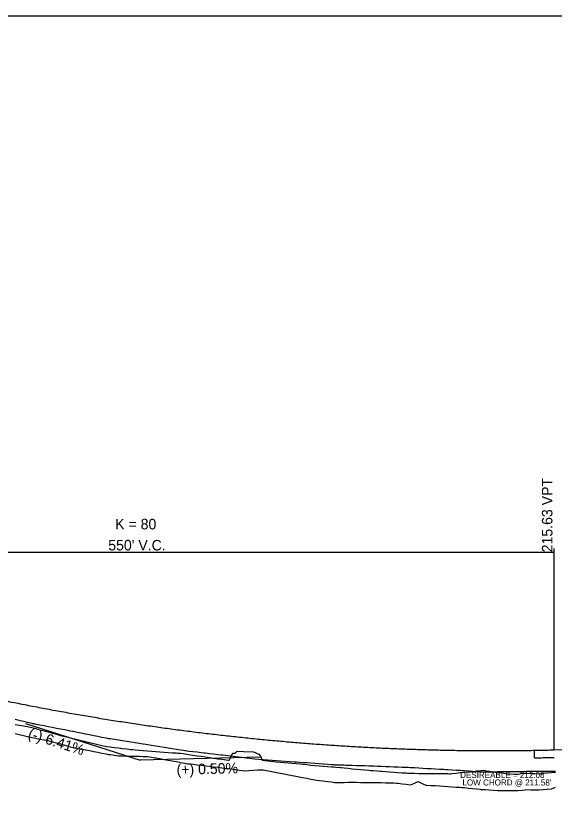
# Model space of a CAD drawing. Extents: x 2224795 to 2228395, y 930927 to 933127.
# Drawn here: x 2226072 to 2226430, y 932027 to 932554 of the extents above; entities that cross this region are included whole.
import ezdxf

# ---------------------------------------------------------------- set-up
doc = ezdxf.new("R2010")
doc.units = 0
for name, color, linetype in [('BR_CONCRETE', 7, 'Continuous'), ('BR_EXIST_GROUND_LT', 7, 'Continuous'), ('BR_EXIST_GROUND_RT', 7, 'Continuous'), ('BR_USER NOTES', 7, 'Continuous'), ('RD_DDB_GradeTX', 7, 'Continuous'), ('RD_DDB_Profile_EX', 7, 'Continuous'), ('RD_DDB_Profile_PR', 7, 'Continuous'), ('RD_DDB_StripGrade', 7, 'Continuous'), ('RD_DDB_VCLbl', 7, 'Continuous'), ('RD_SHT_ShtClip', 7, 'Continuous')]:
    doc.layers.add(name, color=color, linetype=linetype)

msp = doc.modelspace()

# ---------------------------------------------------------------- linework, layer by layer
at = {"layer": 'BR_CONCRETE'}
msp.add_line((2226417.06, 932061.38), (2226417.06, 932066.38), dxfattribs=at)
msp.add_open_spline([(2226417.06, 932061.38), (2226417.06, 932061.38), (2226417.06, 932061.38), (2226417.43, 932061.38), (2226417.8, 932061.39), (2226418.35, 932061.4), (2226418.62, 932061.41), (2226418.94, 932061.41), (2226419.09, 932061.42), (2226419.15, 932061.42), (2226419.17, 932061.42), (2226419.18, 932061.42), (2226419.22, 932061.42), (2226419.97, 932061.44), (2226423.63, 932061.51), (2226427.26, 932061.59), (2226430.17, 932061.66)], degree=3, dxfattribs=at)
at = {"layer": 'BR_EXIST_GROUND_LT'}
msp.add_lwpolyline([(2226071.93, 932077.54), (2226074.68, 932076.9), (2226077.43, 932076.27), (2226080.17, 932075.62), (2226082.92, 932074.98), (2226085.67, 932074.33), (2226088.42, 932073.86), (2226091.17, 932073.39), (2226093.46, 932072.99), (2226093.91, 932072.87), (2226096.66, 932072.11), (2226099.41, 932071.34), (2226102.16, 932070.57), (2226104.91, 932069.8), (2226107.66, 932069.01), (2226110.4, 932068.25), (2226113.15, 932067.74), (2226115.9, 932067.23), (2226116.82, 932067.06), (2226118.65, 932066.7), (2226121.4, 932066.16), (2226124.15, 932065.62), (2226126.89, 932065.07), (2226129.64, 932064.52), (2226132.39, 932063.96), (2226133.68, 932063.69), (2226135.14, 932063.49), (2226137.89, 932063.1), (2226140.64, 932062.71), (2226141.14, 932062.64), (2226143.38, 932062.6), (2226146.13, 932062.55), (2226148.88, 932062.49), (2226151.63, 932062.44), (2226154.38, 932062.38), (2226157.13, 932062.31), (2226159.23, 932062.26), (2226159.87, 932062.21), (2226162.62, 932061.79), (2226164.89, 932061.44), (2226165.37, 932061.36), (2226168.12, 932060.86), (2226170.87, 932060.37), (2226173.61, 932059.87), (2226176.36, 932059.36), (2226179.11, 932058.86), (2226181.86, 932058.35), (2226184.61, 932057.83), (2226185.44, 932057.68), (2226186.41, 932057.49), (2226187.36, 932057.4), (2226190.25, 932057.12), (2226192.85, 932056.81), (2226195.6, 932056.47), (2226198.35, 932056.13), (2226201.1, 932055.79), (2226203.85, 932055.44), (2226206.59, 932055.09), (2226209.34, 932054.73), (2226211.98, 932054.38), (2226213.44, 932054.22), (2226224.38, 932052.72), (2226233.25, 932053.42), (2226236.69, 932053.43), (2226260.77, 932048.71), (2226261.67, 932048.56), (2226262.94, 932048.34), (2226265.7, 932047.8), (2226268.46, 932047.29), (2226271.22, 932046.8), (2226272.56, 932046.58), (2226273.98, 932046.4), (2226276.73, 932046.05), (2226279.49, 932045.69), (2226282.25, 932045.33), (2226284.38, 932045.04), (2226285.01, 932045.05), (2226287.76, 932045.07), (2226290.52, 932045.09), (2226293.28, 932045.1), (2226296.04, 932045.1), (2226298.8, 932045.1), (2226301.55, 932045.09), (2226304.31, 932045.08), (2226307.07, 932045.05), (2226308.3, 932045.04), (2226309.93, 932044.96), (2226312.58, 932044.93), (2226315.34, 932044.88), (2226318.1, 932044.83), (2226320.86, 932044.77), (2226323.65, 932044.71), (2226325.31, 932044.61), (2226326.37, 932044.48), (2226329.13, 932044.14), (2226331.89, 932043.79), (2226334.7, 932043.43), (2226337.02, 932044.39), (2226337.4, 932044.56), (2226339.75, 932045.6), (2226340.16, 932045.42), (2226342.92, 932044.18), (2226344.83, 932043.32), (2226345.68, 932043.27), (2226348.43, 932043.1), (2226351.19, 932042.92), (2226353.95, 932042.72), (2226356.71, 932042.51), (2226359.47, 932042.29), (2226362.32, 932042.04), (2226364.98, 932041.93), (2226367.74, 932041.8), (2226368.77, 932041.75), (2226370.5, 932041.59), (2226373.25, 932041.31), (2226376.01, 932041.01), (2226378.77, 932040.71), (2226380.89, 932040.46), (2226381.53, 932040.42), (2226384.29, 932040.23), (2226387.04, 932040.02), (2226389.8, 932039.81), (2226392.78, 932039.56), (2226395.32, 932039.61), (2226398.07, 932039.66), (2226400.83, 932039.69), (2226403.59, 932039.7), (2226406.35, 932039.72), (2226409.11, 932039.98), (2226411.95, 932040.24), (2226414.62, 932040.2), (2226417.38, 932040.14), (2226419.45, 932040.09), (2226420.14, 932040.14), (2226422.89, 932040.3), (2226425.65, 932040.46), (2226428.41, 932040.71), (2226431.17, 932041.97)], dxfattribs=at)
at = {"layer": 'BR_EXIST_GROUND_RT'}
msp.add_lwpolyline([(2226071.93, 932083.47), (2226074.68, 932083), (2226077.43, 932082.53), (2226080.17, 932082.08), (2226082.92, 932081.63), (2226085.67, 932080.84), (2226088.42, 932080.07), (2226091.17, 932079.3), (2226093.91, 932078.54), (2226096.66, 932077.78), (2226099.41, 932077.04), (2226102.16, 932076.31), (2226104.94, 932075.57), (2226107.32, 932075.08), (2226107.66, 932074.99), (2226110.4, 932074.27), (2226113.15, 932073.55), (2226115.9, 932072.85), (2226118.65, 932072.16), (2226121.4, 932071.48), (2226124.15, 932070.81), (2226126.89, 932070.15), (2226129.64, 932069.5), (2226130.6, 932069.28), (2226131.77, 932069.09), (2226132.52, 932068.92), (2226135.14, 932068.58), (2226137.89, 932068.24), (2226140.64, 932067.91), (2226143.38, 932067.6), (2226146.13, 932067.3), (2226148.88, 932067.01), (2226150.05, 932066.89), (2226151.63, 932066.75), (2226154.38, 932066.51), (2226157.13, 932066.26), (2226159.87, 932066.01), (2226162.5, 932065.77), (2226165.37, 932065.55), (2226168.12, 932065.34), (2226170.87, 932065.14), (2226173.61, 932064.96), (2226176.36, 932064.78), (2226179.11, 932064.62), (2226180.12, 932064.56), (2226181.5, 932064.4), (2226181.86, 932064.37), (2226183.68, 932064.26), (2226184.61, 932064.11), (2226187.36, 932063.66), (2226190.1, 932063.23), (2226192.85, 932062.8), (2226195.6, 932062.38), (2226198.35, 932061.97), (2226201.1, 932061.57), (2226203.85, 932061.18), (2226206.59, 932060.8), (2226207.43, 932060.68), (2226208.14, 932060.65), (2226209.34, 932060.49), (2226213.7, 932059.92), (2226214.13, 932059.91), (2226216.62, 932064.47), (2226218.21, 932064.51), (2226219.43, 932065.84), (2226223.68, 932065.61), (2226230.4, 932065.38), (2226233.87, 932063.74), (2226234.95, 932062.47), (2226236.05, 932059.81), (2226245.41, 932058.77), (2226261.37, 932057.31), (2226262.94, 932057.14), (2226265.7, 932056.85), (2226267.05, 932056.7), (2226268.46, 932056.58), (2226271.22, 932056.35), (2226273.98, 932056.12), (2226276.73, 932055.9), (2226279.49, 932055.69), (2226282.25, 932055.49), (2226283.76, 932055.38), (2226285.01, 932055.25), (2226287.76, 932054.98), (2226288.8, 932054.88), (2226290.52, 932054.69), (2226293.28, 932054.41), (2226296.04, 932054.13), (2226298.8, 932053.86), (2226301.55, 932053.59), (2226304.31, 932053.34), (2226307.07, 932053.09), (2226308.23, 932052.99), (2226309.83, 932052.87), (2226312.58, 932052.66), (2226314.66, 932052.51), (2226315.34, 932052.46), (2226318.1, 932052.25), (2226320.86, 932052.05), (2226323.62, 932051.85), (2226326.37, 932051.67), (2226329.13, 932051.49), (2226331.89, 932051.32), (2226332.64, 932051.28), (2226333.44, 932051.24), (2226334.25, 932051.19), (2226334.65, 932051.18), (2226337.4, 932051.12), (2226340.16, 932051.07), (2226342.92, 932051.02), (2226345.68, 932050.99), (2226348.43, 932050.96), (2226351.19, 932050.94), (2226353.95, 932050.93), (2226356.71, 932050.93), (2226358.5, 932050.93), (2226359.47, 932050.86), (2226360.63, 932050.77), (2226361.3, 932050.73), (2226362.22, 932050.87), (2226364.98, 932051.25), (2226367.74, 932051.64), (2226369.1, 932051.84), (2226370.5, 932051.93), (2226373.25, 932052.15), (2226376.01, 932052.38), (2226378.77, 932052.63), (2226381.53, 932052.9), (2226383.14, 932053.07), (2226384.29, 932052.89), (2226384.81, 932052.81), (2226387.04, 932052.45), (2226389.8, 932052.05), (2226392.56, 932051.67), (2226395.32, 932051.32), (2226398.07, 932050.99), (2226400.83, 932050.7), (2226403.59, 932050.43), (2226405.15, 932050.3), (2226406.35, 932050.55), (2226409.39, 932051.21), (2226411.86, 932051.1), (2226414.62, 932051), (2226417.38, 932050.91), (2226420.14, 932050.85), (2226421.23, 932050.83), (2226423.11, 932051.23), (2226425.65, 932051.44), (2226428.41, 932051.69), (2226431.17, 932051.95)], dxfattribs=at)
at = {"layer": 'RD_DDB_GradeTX'}
for p in [(2226078.88, 932084.19), (2226235.04, 932061.78)]:
    msp.add_line(p, (2226155.06, 932059.78), dxfattribs=at)
at = {"layer": 'RD_DDB_Profile_EX'}
msp.add_lwpolyline([(2226071.93, 932087.09), (2226074.68, 932086.42), (2226077.43, 932085.74), (2226080.17, 932085.06), (2226082.92, 932084.38), (2226083.55, 932084.22), (2226084.3, 932084.08), (2226085.67, 932083.82), (2226088.42, 932083.3), (2226091.17, 932082.77), (2226093.91, 932082.25), (2226096.66, 932081.72), (2226099.41, 932081.19), (2226102.16, 932080.65), (2226104.91, 932080.11), (2226107.66, 932079.57), (2226108.51, 932079.41), (2226109.97, 932079.11), (2226110.4, 932079.03), (2226113.15, 932078.48), (2226115.9, 932077.93), (2226118.65, 932077.38), (2226121.4, 932076.83), (2226124.15, 932076.28), (2226126.89, 932075.72), (2226129.64, 932075.16), (2226132.39, 932074.6), (2226133.75, 932074.32), (2226134.44, 932074.22), (2226135.14, 932074.11), (2226137.89, 932073.69), (2226140.64, 932073.28), (2226143.38, 932072.85), (2226146.13, 932072.43), (2226148.88, 932072), (2226151.63, 932071.58), (2226154.38, 932071.14), (2226157.13, 932070.71), (2226158.72, 932070.46), (2226160.11, 932070.24), (2226162.62, 932069.84), (2226165.37, 932069.4), (2226168.12, 932068.95), (2226170.87, 932068.51), (2226173.61, 932068.06), (2226176.36, 932067.61), (2226179.11, 932067.15), (2226181.86, 932066.7), (2226183.77, 932066.38), (2226184.78, 932066.21), (2226185.24, 932066.15), (2226187.36, 932065.91), (2226190.1, 932065.6), (2226192.85, 932065.28), (2226195.6, 932064.97), (2226197.46, 932064.75), (2226198.35, 932064.65), (2226201.1, 932064.32), (2226203.85, 932063.99), (2226206.59, 932063.66), (2226208.94, 932063.38), (2226209.34, 932063.34), (2226209.8, 932063.29), (2226231.22, 932060.71), (2226233.9, 932060.42), (2226257.32, 932058.77), (2226258.83, 932058.66), (2226262.94, 932058.38), (2226265.7, 932058.18), (2226268.46, 932057.98), (2226271.22, 932057.79), (2226273.98, 932057.59), (2226276.73, 932057.38), (2226279.49, 932057.18), (2226282.25, 932056.97), (2226283.19, 932056.9), (2226283.78, 932056.85), (2226284.46, 932056.8), (2226285.01, 932056.78), (2226287.76, 932056.71), (2226290.52, 932056.62), (2226291.84, 932056.58), (2226293.28, 932056.54), (2226296.04, 932056.45), (2226298.8, 932056.36), (2226301.55, 932056.27), (2226304.31, 932056.18), (2226307.07, 932056.08), (2226309.4, 932056), (2226309.83, 932055.98), (2226310.31, 932055.96), (2226312.58, 932055.88), (2226315.34, 932055.77), (2226318.1, 932055.67), (2226320.86, 932055.56), (2226323.62, 932055.46), (2226326.37, 932055.35), (2226329.13, 932055.23), (2226331.89, 932055.12), (2226333.07, 932055.07), (2226334.65, 932054.99), (2226337.4, 932054.84), (2226340.16, 932054.69), (2226342.92, 932054.54), (2226345.68, 932054.39), (2226348.43, 932054.23), (2226351.19, 932054.07), (2226353.95, 932053.91), (2226356.82, 932053.75), (2226358.08, 932053.68), (2226359.47, 932053.59), (2226362.22, 932053.43), (2226364.98, 932053.26), (2226367.74, 932053.09), (2226370.5, 932052.92), (2226373.25, 932052.75), (2226376.01, 932052.58), (2226378.77, 932052.4), (2226381.53, 932052.23), (2226383.15, 932052.12), (2226384.29, 932052.06), (2226385.94, 932052.09), (2226387.04, 932052.1), (2226389.8, 932052.15), (2226392.56, 932052.19), (2226395.32, 932052.23), (2226398.07, 932052.26), (2226400.83, 932052.3), (2226403.59, 932052.33), (2226406.35, 932052.36), (2226409.28, 932052.39), (2226411.86, 932052.42), (2226414.62, 932052.44), (2226417.38, 932052.47), (2226418.08, 932052.47), (2226420.14, 932052.48), (2226422.89, 932052.49), (2226423.42, 932052.49), (2226423.91, 932052.51), (2226425.65, 932052.52), (2226428.41, 932052.53), (2226431.17, 932052.54)], dxfattribs=at)
at = {"layer": 'RD_DDB_Profile_PR'}
msp.add_line((2226430.06, 932066.65), (2226530.06, 932069.15), dxfattribs=at)
msp.add_spline([(2225880.06, 932147.9), (2225891.06, 932144.42), (2225902.06, 932141.01), (2225913.06, 932137.67), (2225924.06, 932134.41), (2225935.06, 932131.23), (2225946.06, 932128.12), (2225957.06, 932125.09), (2225968.06, 932122.14), (2225979.06, 932119.26), (2225990.06, 932116.45), (2226001.06, 932113.73), (2226012.06, 932111.08), (2226023.06, 932108.5), (2226034.06, 932106), (2226045.06, 932103.58), (2226056.06, 932101.23), (2226067.06, 932098.96), (2226078.06, 932096.77), (2226089.06, 932094.65), (2226100.06, 932092.6), (2226111.06, 932090.64), (2226122.06, 932088.75), (2226133.06, 932086.93), (2226144.06, 932085.19), (2226155.06, 932083.53), (2226166.06, 932081.94), (2226177.06, 932080.43), (2226188.06, 932079), (2226199.06, 932077.64), (2226210.06, 932076.35), (2226221.06, 932075.15), (2226232.06, 932074.02), (2226243.06, 932072.96), (2226254.06, 932071.98), (2226265.06, 932071.08), (2226276.06, 932070.25), (2226287.06, 932069.5), (2226298.06, 932068.83), (2226309.06, 932068.23), (2226320.06, 932067.7), (2226331.06, 932067.26), (2226342.06, 932066.89), (2226353.06, 932066.59), (2226364.06, 932066.37), (2226375.06, 932066.23), (2226386.06, 932066.16), (2226397.06, 932066.17), (2226408.06, 932066.26), (2226419.06, 932066.42), (2226430.06, 932066.65)], degree=3, dxfattribs=at)
at = {"layer": 'RD_DDB_VCLbl'}
for p, q in [((2225880.06, 932197.9), (2226430.06, 932197.9)), ((2226430.06, 932200.4), (2226430.06, 932066.65))]:
    msp.add_line(p, q, dxfattribs=at)
at = {"layer": 'RD_SHT_ShtClip'}
msp.add_lwpolyline([(2225474.62, 932554.3), (2227274.62, 932554.3), (2227274.62, 931454.3), (2225474.62, 931454.3)], close=True, dxfattribs=at)

# ---------------------------------------------------------------- texts
at = {"layer": 'BR_USER NOTES'}
for s, p in [("DESIREABLE = 212.08'", (2226367.72, 932048)), ("LOW CHORD @ 211.58'", (2226369.28, 932043))]:
    msp.add_text(s, height=4, dxfattribs=at).set_placement(p)
at = {"layer": 'RD_DDB_GradeTX'}
for s, rotation, p in [('(-) 6.41%', 342.2315, (2226079.96, 932074.66)), ('(+) 0.50%', 1.4321, (2226179.31, 932050.09))]:
    msp.add_text(s, height=7, rotation=rotation, dxfattribs=at).set_placement(p)
at = {"layer": 'RD_DDB_StripGrade'}
msp.add_text('215.63 VPT', height=7, rotation=90, dxfattribs=at).set_placement((2226429.06, 932197.9))
at = {"layer": 'RD_DDB_VCLbl'}
for s, p in [('K = 80', (2226138.44, 932213.15)), ("550' V.C.", (2226133.81, 932199.15))]:
    msp.add_text(s, height=7, dxfattribs=at).set_placement(p)

doc.saveas('drawing.dxf')
